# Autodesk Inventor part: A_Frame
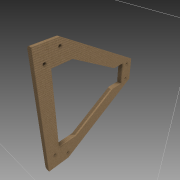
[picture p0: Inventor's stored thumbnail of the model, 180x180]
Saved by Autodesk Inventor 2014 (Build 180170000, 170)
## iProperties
Created: 2013-12
Part Number: A_Frame
Material: MDF Medium Density Fiberboard
Document SubType Name: Modeling
Designer: Bram
Density: 0.8 g/cm^3
Appearance: Cardboard - Corrugated
Author: Bram
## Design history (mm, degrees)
sketch "Sketch1"
  geometry: L1 (303.237, 40.135)-(5.237, 212.185); L2 (-17.986, 139.185)-(41.677, 139.185); L3 (-17.986, 139.185)-(-28.513, 139.185); L4 (-28.513, 139.185)-(-28.513, -0.315); L5 (-28.513, 212.185)-(5.237, 212.185); L6 (5.237, 212.185)-(-74.763, 212.185); L7 (-74.763, 212.185)-(-74.763, -0.315); L8 (258.237, 39.685)-(214.016, 39.685); L9 (214.016, 39.685)-(41.677, 139.185); L10 (303.237, 40.135)-(303.237, -0.315); L11 (258.237, 39.685)-(258.237, -0.315); L12 (303.237, -40.764)-(5.237, -212.815); L13 (214.016, -40.315)-(41.677, -139.815); L14 (-28.513, -139.815)-(-28.513, -0.315); L15 (-17.986, -139.815)-(41.677, -139.815); L16 (-17.986, -139.815)-(-28.513, -139.815); L17 (-28.513, -212.815)-(5.237, -212.815); L18 (5.237, -212.815)-(-74.763, -212.815); L19 (-74.763, -212.815)-(-74.763, -0.315); L20 (258.237, -40.315)-(214.016, -40.315); L21 (303.237, -40.764)-(303.237, -0.315); L22 (258.237, -40.315)-(258.237, -0.315); L23 (-28.513, 139.185)-(41.677, 139.185); L24 (41.677, 139.185)-(214.016, 39.685); L25 (214.016, 39.685)-(258.237, 39.685); L26 (258.237, 39.685)-(258.237, -40.315); L27 (258.237, -40.315)-(214.016, -40.315); L28 (214.016, -40.315)-(41.677, -139.815); L29 (41.677, -139.815)-(-28.513, -139.815); L30 (-28.513, 139.185)-(-28.513, -139.815); L31 (-74.763, 212.185)-(5.237, 212.185); L32 (5.237, 212.185)-(303.237, 40.135); L33 (303.237, 40.135)-(303.237, -40.764); L34 (303.237, -40.764)-(5.237, -212.815); L35 (5.237, -212.815)-(-74.763, -212.815); L36 (-74.763, -212.815)-(-74.763, 212.185); C1 r 5 at (-46.763, 158.685); C2 r 5 at (3.237, 188.185); C3 r 5 at (279.237, 28.685); C4 r 5 at (-46.763, -159.315); C5 r 5 at (3.237, -188.815); C6 r 5 at (279.237, -29.315)
  constraints: 72 end point, 6 centre point, 6 collinear, 5 perpendicular, 3 parallel
extrude "Extrusion1" new body sketch "Sketch1" distance "d34" = 18; taper "d35" = 0 deg
fillet "Fillet1" dims "d36" = 10
body "Solid1"
other parameters: "d0" = 78 (derived), "d2" = 28 (derived), "d4" = 46.25 (derived), "d6" = 288.77876 (derived), "d8" = 333 (derived), "d10" = 354 (derived), "d12" = 378 (derived), "d14" = 40.44962 (derived), "d16" = 29 (derived), "d18" = 44.22124 (derived), "d20" = 24 (derived), "d22" = 53.5 (derived), "d24" = 139.5 (derived), "d26" = 70.18971 (derived), "d28" = 212.5 (derived), "d32" = 73 (derived)
